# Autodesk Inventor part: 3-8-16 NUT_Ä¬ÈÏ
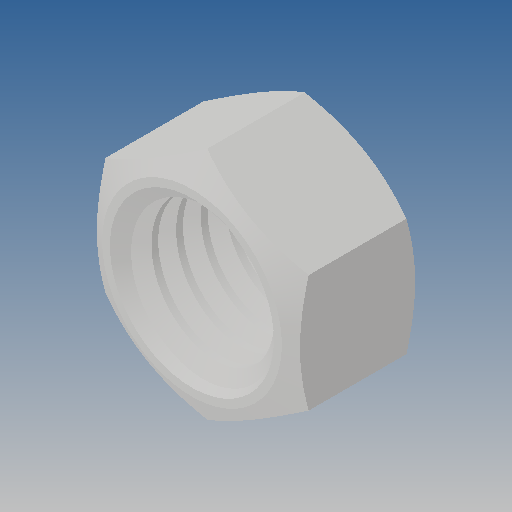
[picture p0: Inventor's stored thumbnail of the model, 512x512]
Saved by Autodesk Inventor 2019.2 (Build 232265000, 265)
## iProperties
Created: 2010-06
Part Number: 3-8-16 NUT_Ä¬ÈÏ
Material: Ogólny
Document SubType Name: Modeling
Designer: CADENGINEERING4
Density: 1 g/cm^3
Appearance: Domyślna
Author: CADENGINEERING4
Revision Number: ÈÎºÎ
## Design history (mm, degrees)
feature "NONE"
node "Bryła1"
